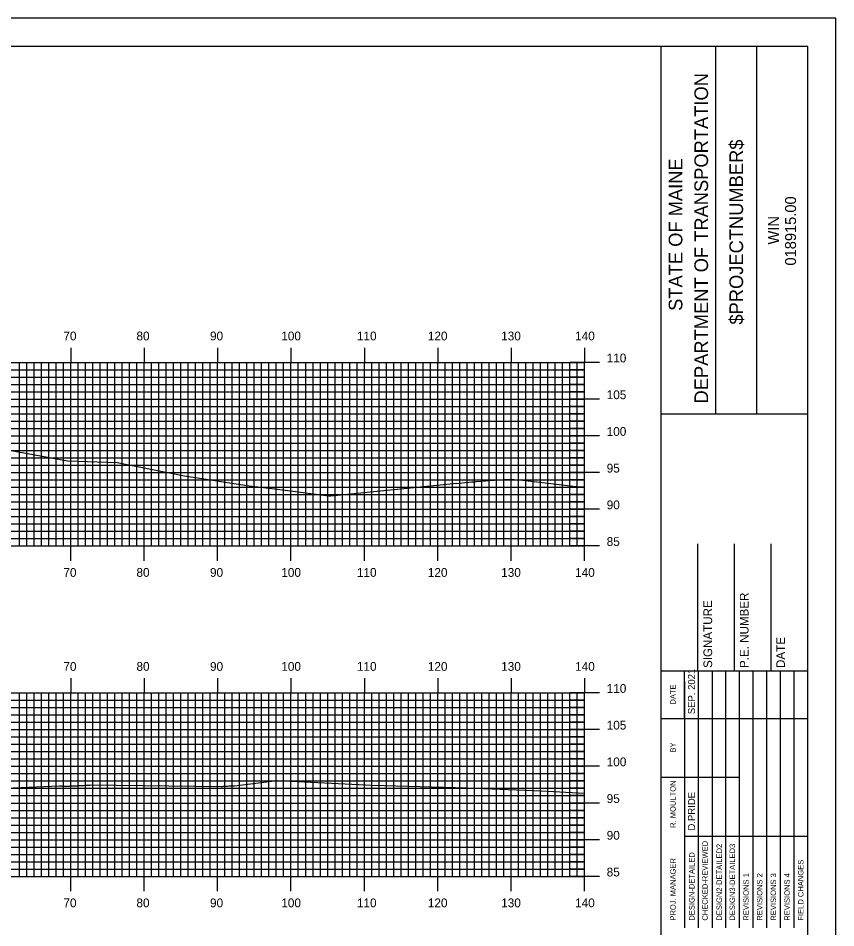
# Model space of a CAD drawing. Extents: x 1774777 to 1775120, y 442591 to 442811.
# Drawn here: x 1775005.5 to 1775116.9, y 442686.7 to 442810.5 of the extents above; entities that cross this region are included whole.
import ezdxf

# ---------------------------------------------------------------- set-up
doc = ezdxf.new("R2010")
doc.units = 0
for name, color, linetype in [('BORDER', 7, 'Continuous'), ('H_V ANNOTATION', 7, 'Continuous'), ('MAJOR', 7, 'Continuous'), ('MINOR', 7, 'Continuous'), ('PLOT BOUNDARY', 7, 'Continuous'), ('S_Roadway_Centerline', 7, 'Continuous')]:
    doc.layers.add(name, color=color, linetype=linetype)

msp = doc.modelspace()

# ---------------------------------------------------------------- linework, layer by layer
at = {"layer": 'BORDER'}
for p, q in [((1775093.09, 442596.67), (1775093.09, 442806.67)), ((1775100.54, 442756.66), (1775100.54, 442806.66)), ((1775106.13, 442756.66), (1775106.13, 442806.66)), ((1775093.09, 442756.65), (1775113.09, 442756.65)), ((1775098.09, 442721.67), (1775098.09, 442738.97)), ((1775103.09, 442721.67), (1775103.09, 442738.97)), ((1775108.09, 442721.67), (1775108.09, 442738.97)), ((1775093.09, 442721.67), (1775113.09, 442721.67))]:
    msp.add_line(p, q, dxfattribs=at)
msp.add_lwpolyline([(1774793.09, 442596.67), (1775113.09, 442596.67), (1775113.09, 442806.67), (1774793.09, 442806.67)], close=True, dxfattribs=at)
for points in [[(1775096.31, 442715.17), (1775096.31, 442721.67)], [(1775098.18, 442686.68), (1775098.18, 442721.67)], [(1775100.04, 442721.67), (1775100.04, 442686.68)], [(1775101.91, 442686.68), (1775101.91, 442721.67)], [(1775103.77, 442686.68), (1775103.77, 442721.67)], [(1775105.63, 442686.68), (1775105.63, 442721.67)], [(1775107.5, 442686.68), (1775107.5, 442721.67)], [(1775109.36, 442686.68), (1775109.36, 442721.67)], [(1775111.22, 442686.68), (1775111.22, 442721.67)], [(1775096.32, 442686.68), (1775096.32, 442720.26)], [(1775093.09, 442715.17), (1775113.09, 442715.17)], [(1775093.09, 442707.17), (1775096.32, 442707.17)], [(1775096.31, 442707.17), (1775103.77, 442707.17)], [(1775096.31, 442699.17), (1775113.09, 442699.17)]]:
    msp.add_lwpolyline(points, dxfattribs=at)
at = {"layer": 'MAJOR'}
for p, q in [((1775012.69, 442765.67), (1775012.69, 442763.67)), ((1775022.69, 442765.67), (1775022.69, 442763.67)), ((1775032.69, 442765.67), (1775032.69, 442763.67)), ((1775042.69, 442765.67), (1775042.69, 442763.67)), ((1775052.69, 442765.67), (1775052.69, 442763.67)), ((1775062.69, 442765.67), (1775062.69, 442763.67)), ((1775072.69, 442765.67), (1775072.69, 442763.67)), ((1775082.69, 442765.67), (1775082.69, 442763.67)), ((1774802.69, 442763.67), (1775082.69, 442763.67)), ((1774802.69, 442763.67), (1775082.69, 442763.67)), ((1775012.69, 442738.67), (1775012.69, 442763.67)), ((1775022.69, 442738.67), (1775022.69, 442763.67)), ((1775032.69, 442738.67), (1775032.69, 442763.67)), ((1775042.69, 442738.67), (1775042.69, 442763.67)), ((1775052.69, 442738.67), (1775052.69, 442763.67)), ((1775062.69, 442738.67), (1775062.69, 442763.67)), ((1775072.69, 442738.67), (1775072.69, 442763.67)), ((1775084.69, 442763.67), (1775080.68, 442763.67)), ((1775082.69, 442738.67), (1775082.69, 442763.67)), ((1775082.69, 442738.67), (1775082.69, 442763.67)), ((1774802.69, 442758.67), (1775082.69, 442758.67)), ((1775084.69, 442758.67), (1775080.68, 442758.67)), ((1774802.69, 442753.67), (1775082.69, 442753.67)), ((1775084.69, 442753.67), (1775080.68, 442753.67)), ((1774802.69, 442748.67), (1775082.69, 442748.67)), ((1775084.69, 442748.67), (1775080.68, 442748.67)), ((1774802.69, 442743.67), (1775082.69, 442743.67)), ((1775084.69, 442743.67), (1775080.68, 442743.67)), ((1774802.69, 442738.67), (1775082.69, 442738.67)), ((1774802.69, 442738.67), (1775082.69, 442738.67)), ((1775012.69, 442736.66), (1775012.69, 442738.67)), ((1775022.69, 442736.66), (1775022.69, 442738.67)), ((1775032.69, 442736.66), (1775032.69, 442738.67)), ((1775042.69, 442736.66), (1775042.69, 442738.67)), ((1775052.69, 442736.66), (1775052.69, 442738.67)), ((1775062.69, 442736.66), (1775062.69, 442738.67)), ((1775072.69, 442736.66), (1775072.69, 442738.67)), ((1775084.69, 442738.67), (1775080.68, 442738.67)), ((1775082.69, 442736.66), (1775082.69, 442738.67)), ((1775012.69, 442720.67), (1775012.69, 442718.67)), ((1775022.69, 442720.67), (1775022.69, 442718.67)), ((1775032.69, 442720.67), (1775032.69, 442718.67)), ((1775042.69, 442720.67), (1775042.69, 442718.67)), ((1775052.69, 442720.67), (1775052.69, 442718.67)), ((1775062.69, 442720.67), (1775062.69, 442718.67)), ((1775072.69, 442720.67), (1775072.69, 442718.67)), ((1775082.69, 442720.67), (1775082.69, 442718.67)), ((1774802.69, 442718.67), (1775082.69, 442718.67)), ((1774802.69, 442718.67), (1775082.69, 442718.67)), ((1775012.69, 442693.67), (1775012.69, 442718.67)), ((1775022.69, 442693.67), (1775022.69, 442718.67)), ((1775032.69, 442693.67), (1775032.69, 442718.67)), ((1775042.69, 442693.67), (1775042.69, 442718.67)), ((1775052.69, 442693.67), (1775052.69, 442718.67)), ((1775062.69, 442693.67), (1775062.69, 442718.67)), ((1775072.69, 442693.67), (1775072.69, 442718.67)), ((1775084.69, 442718.67), (1775080.68, 442718.67)), ((1775082.69, 442693.67), (1775082.69, 442718.67)), ((1775082.69, 442693.67), (1775082.69, 442718.67)), ((1774802.69, 442713.67), (1775082.69, 442713.67)), ((1775084.69, 442713.67), (1775080.68, 442713.67)), ((1774802.69, 442708.67), (1775082.69, 442708.67)), ((1775084.69, 442708.67), (1775080.68, 442708.67)), ((1774802.69, 442703.67), (1775082.69, 442703.67)), ((1775084.69, 442703.67), (1775080.68, 442703.67)), ((1774802.69, 442698.67), (1775082.69, 442698.67)), ((1775084.69, 442698.67), (1775080.68, 442698.67)), ((1774802.69, 442693.67), (1775082.69, 442693.67)), ((1774802.69, 442693.67), (1775082.69, 442693.67)), ((1775012.69, 442691.66), (1775012.69, 442693.67)), ((1775022.69, 442691.66), (1775022.69, 442693.67)), ((1775032.69, 442691.66), (1775032.69, 442693.67)), ((1775042.69, 442691.66), (1775042.69, 442693.67)), ((1775052.69, 442691.66), (1775052.69, 442693.67)), ((1775062.69, 442691.66), (1775062.69, 442693.67)), ((1775072.69, 442691.66), (1775072.69, 442693.67)), ((1775084.69, 442693.67), (1775080.68, 442693.67)), ((1775082.69, 442691.66), (1775082.69, 442693.67))]:
    msp.add_line(p, q, dxfattribs=at)
at = {"layer": 'MINOR'}
for p, q in [((1775005.69, 442738.67), (1775005.69, 442763.67)), ((1775006.69, 442738.67), (1775006.69, 442763.67)), ((1775007.69, 442738.67), (1775007.69, 442763.67)), ((1775008.69, 442738.67), (1775008.69, 442763.67)), ((1775009.69, 442738.67), (1775009.69, 442763.67)), ((1775010.69, 442738.67), (1775010.69, 442763.67)), ((1775011.69, 442738.67), (1775011.69, 442763.67)), ((1775013.69, 442738.67), (1775013.69, 442763.67)), ((1775014.69, 442738.67), (1775014.69, 442763.67)), ((1775015.69, 442738.67), (1775015.69, 442763.67)), ((1775016.69, 442738.67), (1775016.69, 442763.67)), ((1775017.69, 442738.67), (1775017.69, 442763.67)), ((1775018.69, 442738.67), (1775018.69, 442763.67)), ((1775019.69, 442738.67), (1775019.69, 442763.67)), ((1775020.69, 442738.67), (1775020.69, 442763.67)), ((1775021.69, 442738.67), (1775021.69, 442763.67)), ((1775023.69, 442738.67), (1775023.69, 442763.67)), ((1775024.69, 442738.67), (1775024.69, 442763.67)), ((1775025.69, 442738.67), (1775025.69, 442763.67)), ((1775026.69, 442738.67), (1775026.69, 442763.67)), ((1775027.69, 442738.67), (1775027.69, 442763.67)), ((1775028.69, 442738.67), (1775028.69, 442763.67)), ((1775029.69, 442738.67), (1775029.69, 442763.67)), ((1775030.69, 442738.67), (1775030.69, 442763.67)), ((1775031.69, 442738.67), (1775031.69, 442763.67)), ((1775033.69, 442738.67), (1775033.69, 442763.67)), ((1775034.69, 442738.67), (1775034.69, 442763.67)), ((1775035.69, 442738.67), (1775035.69, 442763.67)), ((1775036.69, 442738.67), (1775036.69, 442763.67)), ((1775037.69, 442738.67), (1775037.69, 442763.67)), ((1775038.69, 442738.67), (1775038.69, 442763.67)), ((1775039.69, 442738.67), (1775039.69, 442763.67)), ((1775040.69, 442738.67), (1775040.69, 442763.67)), ((1775041.69, 442738.67), (1775041.69, 442763.67)), ((1775043.69, 442738.67), (1775043.69, 442763.67)), ((1775044.69, 442738.67), (1775044.69, 442763.67)), ((1775045.69, 442738.67), (1775045.69, 442763.67)), ((1775046.69, 442738.67), (1775046.69, 442763.67)), ((1775047.69, 442738.67), (1775047.69, 442763.67)), ((1775048.69, 442738.67), (1775048.69, 442763.67)), ((1775049.69, 442738.67), (1775049.69, 442763.67)), ((1775050.69, 442738.67), (1775050.69, 442763.67)), ((1775051.69, 442738.67), (1775051.69, 442763.67)), ((1775053.69, 442738.67), (1775053.69, 442763.67)), ((1775054.69, 442738.67), (1775054.69, 442763.67)), ((1775055.69, 442738.67), (1775055.69, 442763.67)), ((1775056.69, 442738.67), (1775056.69, 442763.67)), ((1775057.69, 442738.67), (1775057.69, 442763.67)), ((1775058.69, 442738.67), (1775058.69, 442763.67)), ((1775059.69, 442738.67), (1775059.69, 442763.67)), ((1775060.69, 442738.67), (1775060.69, 442763.67)), ((1775061.69, 442738.67), (1775061.69, 442763.67)), ((1775063.69, 442738.67), (1775063.69, 442763.67)), ((1775064.69, 442738.67), (1775064.69, 442763.67)), ((1775065.69, 442738.67), (1775065.69, 442763.67)), ((1775066.69, 442738.67), (1775066.69, 442763.67)), ((1775067.69, 442738.67), (1775067.69, 442763.67)), ((1775068.69, 442738.67), (1775068.69, 442763.67)), ((1775069.69, 442738.67), (1775069.69, 442763.67)), ((1775070.69, 442738.67), (1775070.69, 442763.67)), ((1775071.69, 442738.67), (1775071.69, 442763.67)), ((1775073.69, 442738.67), (1775073.69, 442763.67)), ((1775074.69, 442738.67), (1775074.69, 442763.67)), ((1775075.69, 442738.67), (1775075.69, 442763.67)), ((1775076.69, 442738.67), (1775076.69, 442763.67)), ((1775077.69, 442738.67), (1775077.69, 442763.67)), ((1775078.69, 442738.67), (1775078.69, 442763.67)), ((1775079.69, 442738.67), (1775079.69, 442763.67)), ((1775080.69, 442738.67), (1775080.69, 442763.67)), ((1775081.69, 442738.67), (1775081.69, 442763.67)), ((1774802.69, 442762.67), (1775082.69, 442762.67)), ((1775082.69, 442762.67), (1775080.68, 442762.67)), ((1774802.69, 442761.67), (1775082.69, 442761.67)), ((1775082.69, 442761.67), (1775080.68, 442761.67)), ((1774802.69, 442760.67), (1775082.69, 442760.67)), ((1775082.69, 442760.67), (1775080.68, 442760.67)), ((1774802.69, 442759.67), (1775082.69, 442759.67)), ((1775082.69, 442759.67), (1775080.68, 442759.67)), ((1774802.69, 442757.67), (1775082.69, 442757.67)), ((1775082.69, 442757.67), (1775080.68, 442757.67)), ((1774802.69, 442756.67), (1775082.69, 442756.67)), ((1775082.69, 442756.67), (1775080.68, 442756.67)), ((1774802.69, 442755.67), (1775082.69, 442755.67)), ((1775082.69, 442755.67), (1775080.68, 442755.67)), ((1774802.69, 442754.67), (1775082.69, 442754.67)), ((1775082.69, 442754.67), (1775080.68, 442754.67)), ((1774802.69, 442752.67), (1775082.69, 442752.67)), ((1775082.69, 442752.67), (1775080.68, 442752.67)), ((1774802.69, 442751.67), (1775082.69, 442751.67)), ((1775082.69, 442751.67), (1775080.68, 442751.67)), ((1774802.69, 442750.67), (1775082.69, 442750.67)), ((1775082.69, 442750.67), (1775080.68, 442750.67)), ((1774802.69, 442749.67), (1775082.69, 442749.67)), ((1775082.69, 442749.67), (1775080.68, 442749.67)), ((1774802.69, 442747.67), (1775082.69, 442747.67)), ((1775082.69, 442747.67), (1775080.68, 442747.67)), ((1774802.69, 442746.67), (1775082.69, 442746.67)), ((1775082.69, 442746.67), (1775080.68, 442746.67)), ((1774802.69, 442745.67), (1775082.69, 442745.67)), ((1775082.69, 442745.67), (1775080.68, 442745.67)), ((1774802.69, 442744.67), (1775082.69, 442744.67)), ((1775082.69, 442744.67), (1775080.68, 442744.67)), ((1774802.69, 442742.67), (1775082.69, 442742.67)), ((1775082.69, 442742.67), (1775080.68, 442742.67)), ((1774802.69, 442741.67), (1775082.69, 442741.67)), ((1775082.69, 442741.67), (1775080.68, 442741.67)), ((1774802.69, 442740.67), (1775082.69, 442740.67)), ((1775082.69, 442740.67), (1775080.68, 442740.67)), ((1774802.69, 442739.67), (1775082.69, 442739.67)), ((1775082.69, 442739.67), (1775080.68, 442739.67)), ((1775005.69, 442693.67), (1775005.69, 442718.67)), ((1775006.69, 442693.67), (1775006.69, 442718.67)), ((1775007.69, 442693.67), (1775007.69, 442718.67)), ((1775008.69, 442693.67), (1775008.69, 442718.67)), ((1775009.69, 442693.67), (1775009.69, 442718.67)), ((1775010.69, 442693.67), (1775010.69, 442718.67)), ((1775011.69, 442693.67), (1775011.69, 442718.67)), ((1775013.69, 442693.67), (1775013.69, 442718.67)), ((1775014.69, 442693.67), (1775014.69, 442718.67)), ((1775015.69, 442693.67), (1775015.69, 442718.67)), ((1775016.69, 442693.67), (1775016.69, 442718.67)), ((1775017.69, 442693.67), (1775017.69, 442718.67)), ((1775018.69, 442693.67), (1775018.69, 442718.67)), ((1775019.69, 442693.67), (1775019.69, 442718.67)), ((1775020.69, 442693.67), (1775020.69, 442718.67)), ((1775021.69, 442693.67), (1775021.69, 442718.67)), ((1775023.69, 442693.67), (1775023.69, 442718.67)), ((1775024.69, 442693.67), (1775024.69, 442718.67)), ((1775025.69, 442693.67), (1775025.69, 442718.67)), ((1775026.69, 442693.67), (1775026.69, 442718.67)), ((1775027.69, 442693.67), (1775027.69, 442718.67)), ((1775028.69, 442693.67), (1775028.69, 442718.67)), ((1775029.69, 442693.67), (1775029.69, 442718.67)), ((1775030.69, 442693.67), (1775030.69, 442718.67)), ((1775031.69, 442693.67), (1775031.69, 442718.67)), ((1775033.69, 442693.67), (1775033.69, 442718.67)), ((1775034.69, 442693.67), (1775034.69, 442718.67)), ((1775035.69, 442693.67), (1775035.69, 442718.67)), ((1775036.69, 442693.67), (1775036.69, 442718.67)), ((1775037.69, 442693.67), (1775037.69, 442718.67)), ((1775038.69, 442693.67), (1775038.69, 442718.67)), ((1775039.69, 442693.67), (1775039.69, 442718.67)), ((1775040.69, 442693.67), (1775040.69, 442718.67)), ((1775041.69, 442693.67), (1775041.69, 442718.67)), ((1775043.69, 442693.67), (1775043.69, 442718.67)), ((1775044.69, 442693.67), (1775044.69, 442718.67)), ((1775045.69, 442693.67), (1775045.69, 442718.67)), ((1775046.69, 442693.67), (1775046.69, 442718.67)), ((1775047.69, 442693.67), (1775047.69, 442718.67)), ((1775048.69, 442693.67), (1775048.69, 442718.67)), ((1775049.69, 442693.67), (1775049.69, 442718.67)), ((1775050.69, 442693.67), (1775050.69, 442718.67)), ((1775051.69, 442693.67), (1775051.69, 442718.67)), ((1775053.69, 442693.67), (1775053.69, 442718.67)), ((1775054.69, 442693.67), (1775054.69, 442718.67)), ((1775055.69, 442693.67), (1775055.69, 442718.67)), ((1775056.69, 442693.67), (1775056.69, 442718.67)), ((1775057.69, 442693.67), (1775057.69, 442718.67)), ((1775058.69, 442693.67), (1775058.69, 442718.67)), ((1775059.69, 442693.67), (1775059.69, 442718.67)), ((1775060.69, 442693.67), (1775060.69, 442718.67)), ((1775061.69, 442693.67), (1775061.69, 442718.67)), ((1775063.69, 442693.67), (1775063.69, 442718.67)), ((1775064.69, 442693.67), (1775064.69, 442718.67)), ((1775065.69, 442693.67), (1775065.69, 442718.67)), ((1775066.69, 442693.67), (1775066.69, 442718.67)), ((1775067.69, 442693.67), (1775067.69, 442718.67)), ((1775068.69, 442693.67), (1775068.69, 442718.67)), ((1775069.69, 442693.67), (1775069.69, 442718.67)), ((1775070.69, 442693.67), (1775070.69, 442718.67)), ((1775071.69, 442693.67), (1775071.69, 442718.67)), ((1775073.69, 442693.67), (1775073.69, 442718.67)), ((1775074.69, 442693.67), (1775074.69, 442718.67)), ((1775075.69, 442693.67), (1775075.69, 442718.67)), ((1775076.69, 442693.67), (1775076.69, 442718.67)), ((1775077.69, 442693.67), (1775077.69, 442718.67)), ((1775078.69, 442693.67), (1775078.69, 442718.67)), ((1775079.69, 442693.67), (1775079.69, 442718.67)), ((1775080.69, 442693.67), (1775080.69, 442718.67)), ((1775081.69, 442693.67), (1775081.69, 442718.67)), ((1774802.69, 442717.67), (1775082.69, 442717.67)), ((1774802.69, 442716.67), (1775082.69, 442716.67)), ((1775082.69, 442717.67), (1775080.68, 442717.67)), ((1775082.69, 442716.67), (1775080.68, 442716.67)), ((1774802.69, 442715.67), (1775082.69, 442715.67)), ((1775082.69, 442715.67), (1775080.68, 442715.67)), ((1774802.69, 442714.67), (1775082.69, 442714.67)), ((1775082.69, 442714.67), (1775080.68, 442714.67)), ((1774802.69, 442712.67), (1775082.69, 442712.67)), ((1774802.69, 442711.67), (1775082.69, 442711.67)), ((1775082.69, 442712.67), (1775080.68, 442712.67)), ((1775082.69, 442711.67), (1775080.68, 442711.67)), ((1774802.69, 442710.67), (1775082.69, 442710.67)), ((1775082.69, 442710.67), (1775080.68, 442710.67)), ((1774802.69, 442709.67), (1775082.69, 442709.67)), ((1775082.69, 442709.67), (1775080.68, 442709.67)), ((1774802.69, 442707.67), (1775082.69, 442707.67)), ((1774802.69, 442706.67), (1775082.69, 442706.67)), ((1775082.69, 442707.67), (1775080.68, 442707.67)), ((1775082.69, 442706.67), (1775080.68, 442706.67)), ((1774802.69, 442705.67), (1775082.69, 442705.67)), ((1775082.69, 442705.67), (1775080.68, 442705.67)), ((1774802.69, 442704.67), (1775082.69, 442704.67)), ((1775082.69, 442704.67), (1775080.68, 442704.67)), ((1774802.69, 442702.67), (1775082.69, 442702.67)), ((1774802.69, 442701.67), (1775082.69, 442701.67)), ((1775082.69, 442702.67), (1775080.68, 442702.67)), ((1775082.69, 442701.67), (1775080.68, 442701.67)), ((1774802.69, 442700.67), (1775082.69, 442700.67)), ((1775082.69, 442700.67), (1775080.68, 442700.67)), ((1774802.69, 442699.67), (1775082.69, 442699.67)), ((1775082.69, 442699.67), (1775080.68, 442699.67)), ((1774802.69, 442697.67), (1775082.69, 442697.67)), ((1774802.69, 442696.67), (1775082.69, 442696.67)), ((1775082.69, 442697.67), (1775080.68, 442697.67)), ((1775082.69, 442696.67), (1775080.68, 442696.67)), ((1774802.69, 442695.67), (1775082.69, 442695.67)), ((1775082.69, 442695.67), (1775080.68, 442695.67)), ((1774802.69, 442694.67), (1775082.69, 442694.67)), ((1775082.69, 442694.67), (1775080.68, 442694.67))]:
    msp.add_line(p, q, dxfattribs=at)
at = {"layer": 'PLOT BOUNDARY'}
msp.add_lwpolyline([(1774776.9, 442590.55), (1775116.9, 442590.55), (1775116.9, 442810.55), (1774776.9, 442810.55)], close=True, dxfattribs=at)
at = {"layer": 'S_Roadway_Centerline'}
for points in [[(1775004.08, 442751.78), (1775012.23, 442750.26), (1775019.01, 442750.02), (1775028.19, 442748.21), (1775036.98, 442746.87), (1775040.49, 442746.46), (1775046.78, 442745.65), (1775047.43, 442745.54), (1775047.44, 442745.54), (1775047.44, 442745.54), (1775047.72, 442745.53), (1775047.84, 442745.52), (1775047.94, 442745.52), (1775048.04, 442745.51), (1775048.11, 442745.5), (1775064.81, 442747.16), (1775065.69, 442747.24), (1775066.38, 442747.3), (1775066.91, 442747.35), (1775067.32, 442747.39), (1775067.64, 442747.42), (1775067.88, 442747.44), (1775067.97, 442747.45), (1775072.22, 442747.77), (1775073.84, 442747.7), (1775082.69, 442746.63)], [(1774993.47, 442705.24), (1775011.13, 442706), (1775011.21, 442706), (1775011.31, 442705.99), (1775011.4, 442705.99), (1775011.5, 442705.98), (1775011.61, 442705.98), (1775011.7, 442705.98), (1775011.8, 442705.97), (1775011.88, 442705.97), (1775011.95, 442705.97), (1775012.07, 442705.97), (1775012.2, 442705.97), (1775012.35, 442705.98), (1775012.52, 442705.98), (1775012.69, 442705.99), (1775012.86, 442705.99), (1775013.03, 442706), (1775013.19, 442706), (1775013.33, 442706.01), (1775013.46, 442706.01), (1775013.57, 442706.02), (1775013.71, 442706.03), (1775013.86, 442706.04), (1775014.04, 442706.05), (1775014.23, 442706.06), (1775014.42, 442706.07), (1775014.61, 442706.08), (1775014.79, 442706.09), (1775014.96, 442706.1), (1775015.12, 442706.11), (1775015.25, 442706.12), (1775015.36, 442706.13), (1775033.2, 442705.94), (1775033.34, 442705.94), (1775033.5, 442705.95), (1775033.68, 442705.96), (1775033.86, 442705.97), (1775034.06, 442705.98), (1775034.24, 442705.99), (1775034.42, 442706), (1775034.59, 442706.01), (1775034.75, 442706.01), (1775034.88, 442706.02), (1775034.98, 442706.03), (1775040.83, 442706.73), (1775053.73, 442706.08), (1775066.69, 442705.73), (1775076.76, 442705.34), (1775082.69, 442705.01)]]:
    msp.add_lwpolyline(points, dxfattribs=at)

# ---------------------------------------------------------------- texts
at = {"layer": 'BORDER'}
for s, height, p in [('DEPARTMENT OF TRANSPORTATION', 1.8635, (1775099.5, 442758.08)), ('$PROJECTNUMBER$', 1.8635, (1775104.27, 442768.82)), ('STATE OF MAINE', 1.8635, (1775096, 442770.69)), ('018915.00', 1.491, (1775111.48, 442776.86)), ('WIN', 1.491, (1775109.16, 442779.73)), ('P.E. NUMBER', 1.1811, (1775105.01, 442722.06)), ('SIGNATURE', 1.181, (1775100.05, 442722.06)), ('DATE', 1.181, (1775109.97, 442722.06)), ('SEP. 2021', 0.969, (1775097.73, 442715.76)), ('DATE', 0.743, (1775095.09, 442717.08)), ('BY', 0.743, (1775095.09, 442710.54)), ('R. MOULTON', 0.745, (1775095.09, 442700.28)), ('D.PRIDE', 0.969, (1775097.73, 442699.92)), ('CHECKED-REVIEWED', 0.7455, (1775099.45, 442687.65)), ('DESIGN2-DETAILED2', 0.7455, (1775101.39, 442687.65)), ('DESIGN3-DETAILED3', 0.7455, (1775103.17, 442687.65)), ('PROJ. MANAGER', 0.7455, (1775095.09, 442687.65)), ('DESIGN-DETAILED', 0.7455, (1775097.66, 442687.65)), ('FIELD CHANGES', 0.7455, (1775112.49, 442687.65)), ('REVISIONS 1', 0.7455, (1775105.04, 442687.65)), ('REVISIONS 2', 0.7455, (1775106.9, 442687.65)), ('REVISIONS 3', 0.7455, (1775108.76, 442687.65)), ('REVISIONS 4', 0.7455, (1775110.63, 442687.65))]:
    msp.add_text(s, height=height, rotation=90, dxfattribs=at).set_placement(p)
at = {"layer": 'H_V ANNOTATION'}
for s, p in [('70', (1775011.69, 442766.67)), ('80', (1775021.64, 442766.67)), ('90', (1775031.66, 442766.67)), ('100', (1775041.37, 442766.67)), ('110', (1775051.67, 442766.67)), ('120', (1775061.33, 442766.67)), ('130', (1775071.32, 442766.67)), ('140', (1775081.39, 442766.67)), ('110', (1775085.69, 442763.67)), ('105', (1775085.69, 442758.67)), ('100', (1775085.69, 442753.67)), ('95', (1775085.69, 442748.67)), ('90', (1775085.69, 442743.67)), ('85', (1775085.69, 442738.67)), ('70', (1775011.69, 442734.47)), ('80', (1775021.64, 442734.47)), ('90', (1775031.66, 442734.47)), ('100', (1775041.37, 442734.47)), ('110', (1775051.67, 442734.47)), ('120', (1775061.33, 442734.47)), ('130', (1775071.32, 442734.47)), ('140', (1775081.39, 442734.47)), ('70', (1775011.69, 442721.67)), ('80', (1775021.64, 442721.67)), ('90', (1775031.66, 442721.67)), ('100', (1775041.37, 442721.67)), ('110', (1775051.67, 442721.67)), ('120', (1775061.33, 442721.67)), ('130', (1775071.32, 442721.67)), ('140', (1775081.39, 442721.67)), ('110', (1775085.69, 442718.67)), ('105', (1775085.69, 442713.67)), ('100', (1775085.69, 442708.67)), ('95', (1775085.69, 442703.67)), ('90', (1775085.69, 442698.67)), ('85', (1775085.69, 442693.67)), ('70', (1775011.69, 442689.47)), ('80', (1775021.64, 442689.47)), ('90', (1775031.66, 442689.47)), ('100', (1775041.37, 442689.47)), ('110', (1775051.67, 442689.47)), ('120', (1775061.33, 442689.47)), ('130', (1775071.32, 442689.47)), ('140', (1775081.39, 442689.47))]:
    msp.add_text(s, height=1.2, dxfattribs=at).set_placement(p)

doc.saveas('drawing.dxf')
